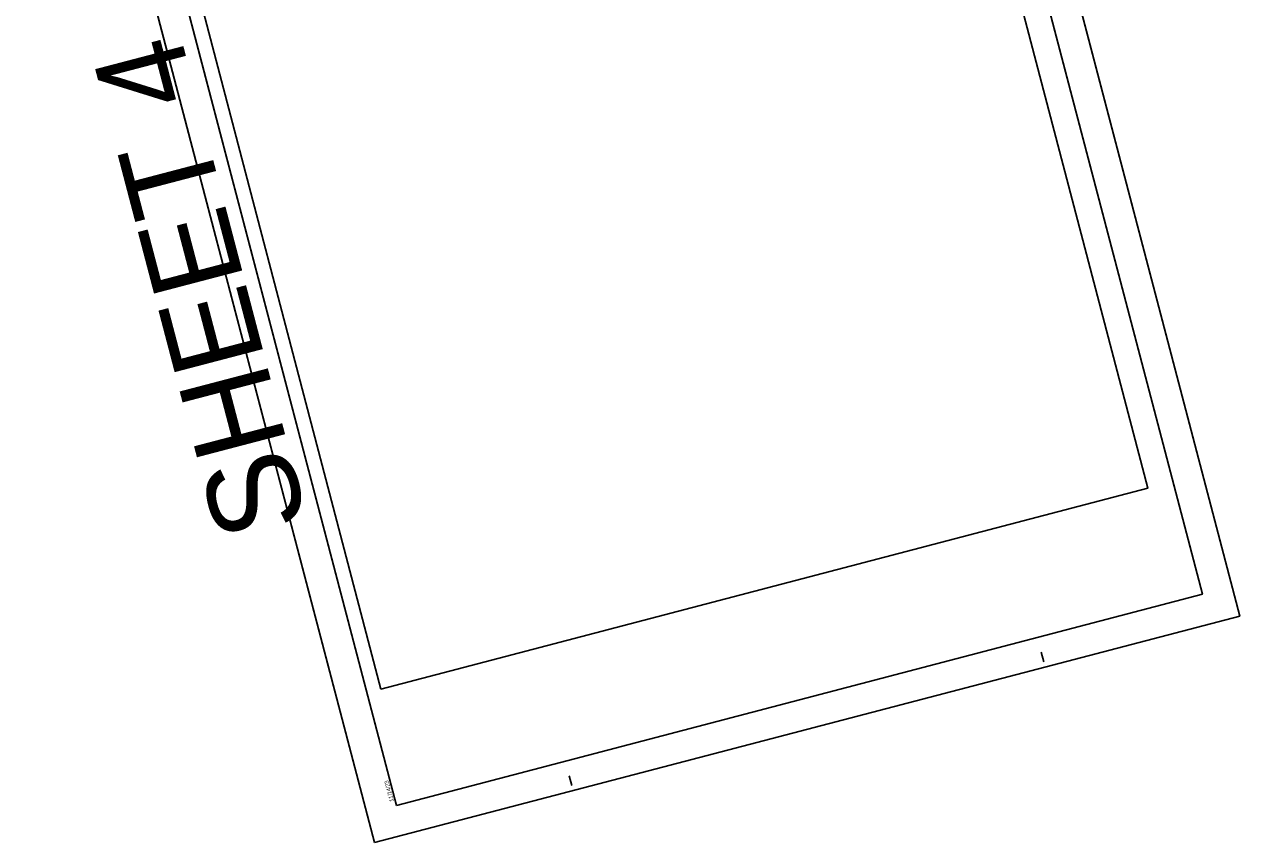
# Model space of a CAD drawing. Extents: x 1366711 to 1368206, y 878140 to 880064.
# Drawn here: x 1366711 to 1368206, y 878140 to 879147 of the extents above; entities that cross this region are included whole.
import ezdxf

# ---------------------------------------------------------------- set-up
doc = ezdxf.new("R2010")
doc.units = 0
for name, color, linetype in [('Exist Environmental Wetland Boundary Cogo Point CELL', 7, 'Continuous'), ('Exist Hydro Jurisdictional Stream or Body of Water Mitigable Cogo Number', 7, 'Continuous'), ('Exist Hydro Jurisdictional Stream or Body of Water NonMitigable', 7, 'Continuous'), ('Raster_Level_0', 7, 'Continuous'), ('Sheet_Data_Text_CELL', 7, 'Continuous'), ('Sheet_Plan_CELL', 7, 'Continuous')]:
    doc.layers.add(name, color=color, linetype=linetype)

msp = doc.modelspace()

# ---------------------------------------------------------------- linework, layer by layer
at = {"layer": 'Exist Environmental Wetland Boundary Cogo Point CELL'}
msp.add_lwpolyline([(1367149.6, 878329.3), (1366870, 879396.1), (1367795.9, 879709.6), (1368092.9, 878576.5)], close=True, dxfattribs=at)
at = {"layer": 'Exist Hydro Jurisdictional Stream or Body of Water Mitigable Cogo Number'}
for p, q in [((1368160.1, 878446.1), (1367748.1, 880018)), ((1366756.6, 879758.2), (1367168.6, 878186.2)), ((1368160.1, 878446.1), (1367168.6, 878186.2)), ((1367964.8, 878362.9), (1367961.6, 878375)), ((1367384.4, 878210.8), (1367381.2, 878222.9)), ((1367153.7, 878213.3), (1367153.7, 878213.3))]:
    msp.add_line(p, q, dxfattribs=at)
at = {"layer": 'Exist Hydro Jurisdictional Stream or Body of Water NonMitigable'}
for p, q in [((1368205.9, 878419.3), (1367774.9, 880063.8)), ((1367141.8, 878140.5), (1366710.8, 879784.9)), ((1368205.9, 878419.3), (1367141.8, 878140.5))]:
    msp.add_line(p, q, dxfattribs=at)
at = {"layer": 'Raster_Level_0'}
msp.add_line((1368205.9, 878419.3), (1368205.9, 878419.3), dxfattribs=at)
at = {"layer": 'Sheet_Data_Text_CELL'}
msp.add_lwpolyline([(1367141.8, 878140.5), (1366710.8, 879784.9), (1367774.9, 880063.8), (1368205.9, 878419.3)], close=True, dxfattribs=at)
at = {"layer": 'Sheet_Plan_CELL'}
msp.add_lwpolyline([(1367168.6, 878186.2), (1366782, 879661.4), (1367773.5, 879921.3), (1368160.1, 878446.1)], close=True, dxfattribs=at)

# ---------------------------------------------------------------- texts
at = {"layer": 'Exist Environmental Wetland Boundary Cogo Point CELL'}
msp.add_text('SHEET 4', height=112.11, rotation=104.6851, dxfattribs=at).set_placement((1367060.1, 878534.4))
at = {"layer": 'Exist Hydro Jurisdictional Stream or Body of Water Mitigable Cogo Number'}
msp.add_text('11/14/23', height=5, rotation=104.6851, dxfattribs=at).set_placement((1367165.3, 878191.5))

doc.saveas('drawing.dxf')
